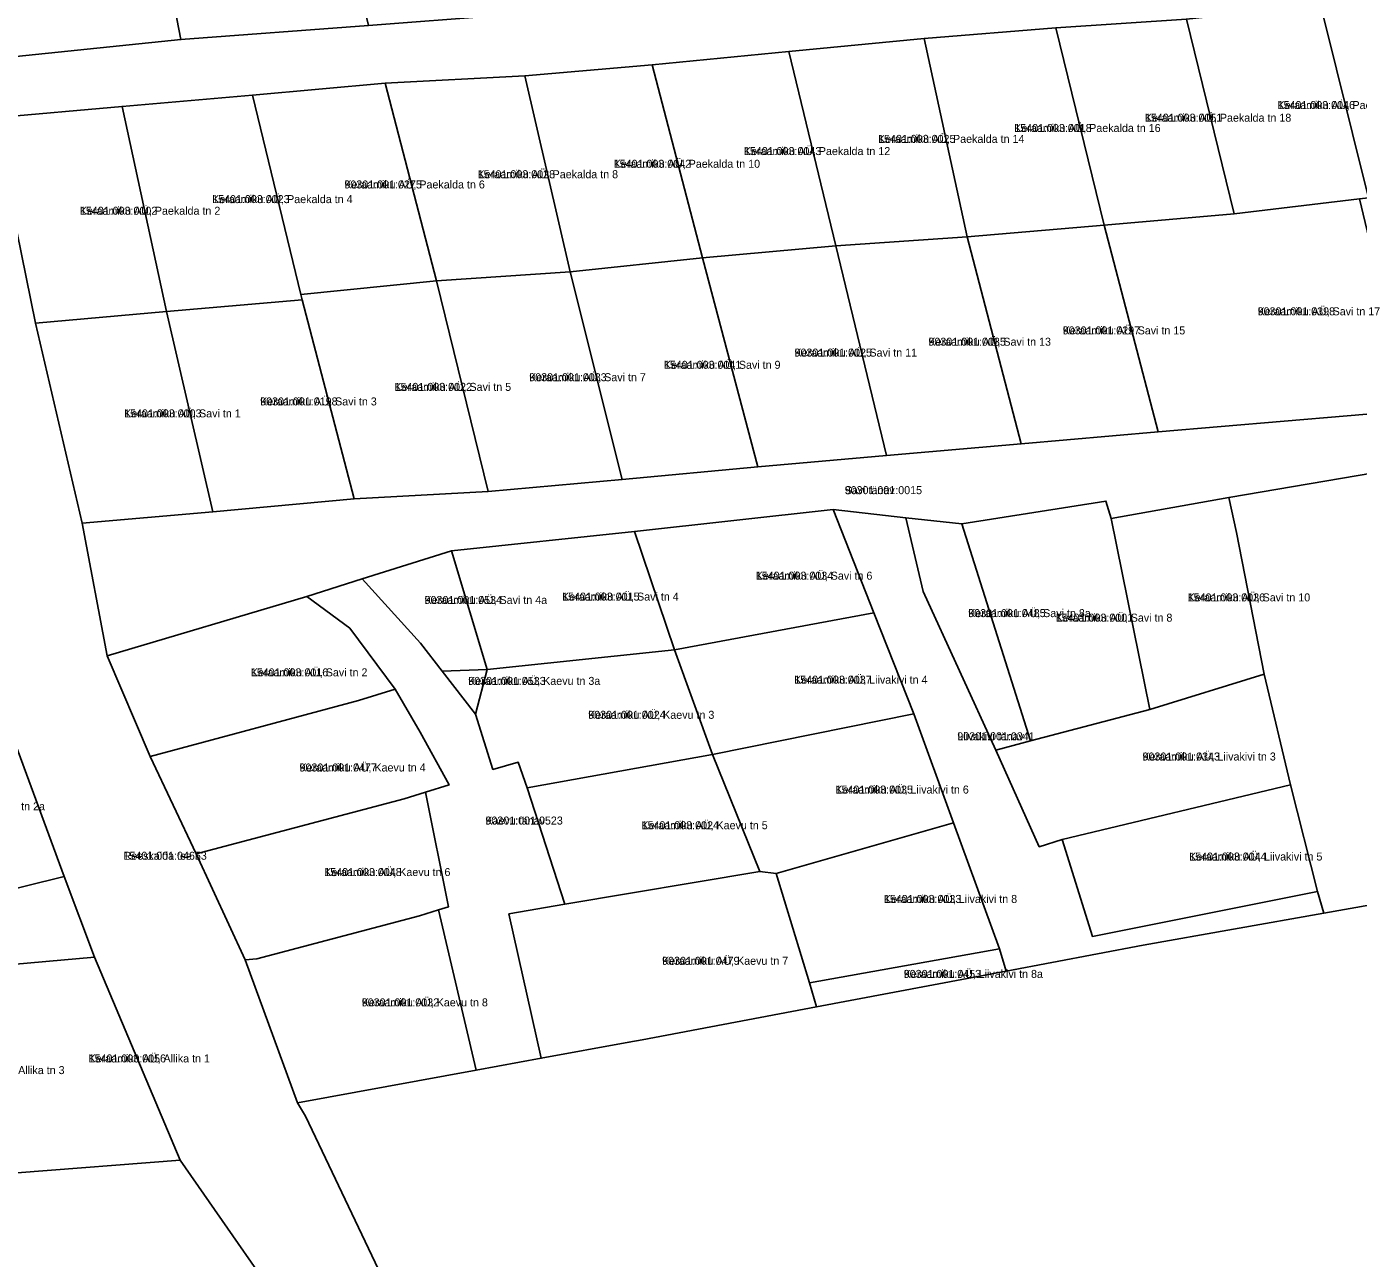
# Model space of a CAD drawing. Extents: x 634518 to 667988, y 6584667 to 6604739.
# Drawn here: x 661923.2 to 662172.8, y 6594554.3 to 6594785.3 of the extents above; entities that cross this region are included whole.
import ezdxf

# ---------------------------------------------------------------- set-up
doc = ezdxf.new("R2010")
doc.units = 0
for name, color, linetype in [('L_AADRESS', 7, 'Continuous'), ('PIIR', 7, 'Continuous'), ('TUNNUS', 7, 'Continuous')]:
    doc.layers.add(name, color=color, linetype=linetype)

msp = doc.modelspace()

# ---------------------------------------------------------------- linework, layer by layer
at = {"layer": 'PIIR'}
for points in [[(661952.09, 6594782.9), (661947.1, 6594808.82), (661942.68, 6594831.72), (661970.02, 6594852.22), (661977.67, 6594824.39), (661987.24, 6594785.58)], [(661911.46, 6594778.72), (661905.34, 6594803.37), (661947.1, 6594808.82), (661952.09, 6594782.9)], [(662165.72, 6594789.4), (662190.16, 6594792.35), (662199.81, 6594755.95), (662174.73, 6594753.23)], [(662149.5, 6594750.24), (662140.59, 6594786.76), (662165.72, 6594789.4), (662174.73, 6594753.23), (662173.04, 6594753.04)], [(662125.18, 6594748.13), (662116.11, 6594785.1), (662140.59, 6594786.76), (662149.5, 6594750.24)], [(662099.49, 6594745.92), (662091.44, 6594783.13), (662116.11, 6594785.1), (662125.18, 6594748.13)], [(662074.83, 6594744.25), (662066.07, 6594780.67), (662091.44, 6594783.13), (662099.49, 6594745.92)], [(662049.88, 6594741.95), (662040.43, 6594778.16), (662066.07, 6594780.67), (662074.83, 6594744.25)], [(661999.99, 6594737.67), (661990.4, 6594774.76), (662016.57, 6594776.09), (662025.06, 6594739.34)], [(662025.06, 6594739.34), (662016.57, 6594776.09), (662040.43, 6594778.16), (662049.88, 6594741.95)], [(661974.6, 6594735.09), (661965.51, 6594772.47), (661990.4, 6594774.76), (661999.99, 6594737.67)], [(661974.84, 6594734.11), (661949.38, 6594731.92), (661941.08, 6594770.36), (661965.51, 6594772.47), (661974.6, 6594735.09)], [(661924.83, 6594729.7), (661916.96, 6594768.23), (661941.08, 6594770.36), (661949.38, 6594731.92)], [(662125.18, 6594748.13), (662149.5, 6594750.24), (662173.04, 6594753.04), (662182.52, 6594713.33), (662135.29, 6594709.35)], [(662135.29, 6594709.35), (662109.62, 6594707.1), (662099.49, 6594745.92), (662125.18, 6594748.13)], [(662049.88, 6594741.95), (662074.83, 6594744.25), (662084.35, 6594704.88), (662060.21, 6594702.77)], [(662074.83, 6594744.25), (662099.49, 6594745.92), (662109.62, 6594707.1), (662084.35, 6594704.88)], [(662034.81, 6594700.43), (662025.06, 6594739.34), (662049.88, 6594741.95), (662060.21, 6594702.77)], [(661999.99, 6594737.67), (662025.06, 6594739.34), (662034.81, 6594700.43), (662009.7, 6594698.16)], [(661974.84, 6594734.11), (661974.6, 6594735.09), (661999.99, 6594737.67), (662009.7, 6594698.16), (661984.55, 6594696.76)], [(661984.55, 6594696.76), (661958.1, 6594694.36), (661949.38, 6594731.92), (661974.84, 6594734.11)], [(661933.59, 6594692.24), (661924.83, 6594729.7), (661949.38, 6594731.92), (661958.1, 6594694.36)], [(662196.65, 6594705.21), (662201.4, 6594681.4), (662236.27, 6594687.1), (662242.98, 6594666.15), (662275.07, 6594673.58), (662277.42, 6594667.41), (662287.3, 6594641.44), (662251.35, 6594634.61), (662246.53, 6594652.01), (662219.88, 6594646.85), (662223.58, 6594629.34), (662214.23, 6594627.56), (662166.33, 6594619.08), (662165.14, 6594623.17), (662160.09, 6594643.16), (662155.13, 6594663.88), (662149.98, 6594690.46), (662148.5, 6594697.01)], [(662111.38, 6594651.37), (662098.46, 6594692.08), (662125.49, 6594696.37), (662126.49, 6594693.07), (662133.73, 6594657.27)], [(662126.49, 6594693.07), (662148.5, 6594697.01), (662149.98, 6594690.46), (662155.13, 6594663.88), (662133.73, 6594657.27)], [(662037.15, 6594690.63), (662074.34, 6594694.77), (662081.99, 6594675.42), (662044.61, 6594668.48)], [(662117.26, 6594632.91), (662122.95, 6594614.73), (662165.14, 6594623.17), (662166.33, 6594619.08), (662132.48, 6594613.08), (662106.77, 6594608.23), (662105.54, 6594612.38), (662096.93, 6594636.02), (662089.46, 6594656.48), (662081.99, 6594675.42), (662074.34, 6594694.77), (662087.97, 6594693.25), (662091.24, 6594679.41), (662104.83, 6594649.65), (662112.99, 6594631.55)], [(662098.46, 6594692.08), (662111.38, 6594651.37), (662104.83, 6594649.65), (662091.24, 6594679.41), (662087.97, 6594693.25)], [(662002.83, 6594687.04), (662037.15, 6594690.63), (662044.61, 6594668.48), (662009.48, 6594664.76)], [(661986.08, 6594681.76), (662002.83, 6594687.04), (662009.48, 6594664.76), (662001.07, 6594664.47), (661997, 6594669.7)], [(661975.68, 6594678.48), (661986.08, 6594681.76), (661997, 6594669.7), (662001.07, 6594664.47), (662007.32, 6594656.43), (662010.57, 6594646.04), (662015.33, 6594647.39), (662016.98, 6594642.58), (662024.04, 6594620.8), (662013.58, 6594618.94), (662019.64, 6594591.87), (662007.46, 6594589.64), (662000.39, 6594619.68), (662002.23, 6594620.25), (661997.93, 6594641.79), (662002.37, 6594643.12), (661996.93, 6594653.01), (661992.27, 6594661.09), (661983.76, 6594672.52)], [(661946.35, 6594648.49), (661938.29, 6594667.33), (661975.68, 6594678.48), (661983.76, 6594672.52), (661992.27, 6594661.09), (661985.42, 6594658.98)], [(662051.73, 6594648.83), (662044.61, 6594668.48), (662081.99, 6594675.42), (662089.46, 6594656.48)], [(661772.99, 6594666.58), (661777.22, 6594667.05), (661784.51, 6594671.09), (661784.65, 6594668.87), (661786.84, 6594636.17), (661786.72, 6594613.48), (661829.26, 6594616.38), (661871.06, 6594617.08), (661885.08, 6594618.37), (661907.96, 6594620.48), (661930.24, 6594625.96), (661935.9, 6594610.85), (661917.6, 6594609.21), (661893.7, 6594606.91), (661868.98, 6594606.11), (661844.31, 6594605.15), (661819.12, 6594604.56), (661794.19, 6594601.28), (661770.12, 6594599.82), (661769.01, 6594610.95), (661778.3, 6594611.7), (661776.11, 6594638.94)], [(662009.48, 6594664.76), (662044.61, 6594668.48), (662051.73, 6594648.83), (662016.98, 6594642.58), (662015.33, 6594647.39), (662010.57, 6594646.04), (662007.32, 6594656.43)], [(662001.07, 6594664.47), (662009.48, 6594664.76), (662007.32, 6594656.43)], [(662133.73, 6594657.27), (662155.13, 6594663.88), (662160.09, 6594643.16), (662117.26, 6594632.91), (662112.99, 6594631.55), (662104.83, 6594649.65), (662111.38, 6594651.37)], [(661946.35, 6594648.49), (661985.42, 6594658.98), (661992.27, 6594661.09), (661996.93, 6594653.01), (662002.37, 6594643.12), (661997.93, 6594641.79), (661993.97, 6594640.55), (661954.96, 6594630.21)], [(661918.31, 6594658.38), (661930.24, 6594625.96), (661907.96, 6594620.48), (661885.08, 6594618.37), (661877.59, 6594645.87), (661910.92, 6594655.93)], [(662051.73, 6594648.83), (662089.46, 6594656.48), (662096.93, 6594636.02), (662063.65, 6594626.54), (662060.61, 6594626.92)], [(662024.04, 6594620.8), (662016.98, 6594642.58), (662051.73, 6594648.83), (662060.61, 6594626.92)], [(661966.31, 6594610.54), (661964.17, 6594610.3), (661954.96, 6594630.21), (661993.97, 6594640.55), (661997.93, 6594641.79), (662002.23, 6594620.25), (662000.39, 6594619.68), (661996.85, 6594618.58)], [(662122.95, 6594614.73), (662117.26, 6594632.91), (662160.09, 6594643.16), (662165.14, 6594623.17)], [(662069.93, 6594605.99), (662063.65, 6594626.54), (662096.93, 6594636.02), (662105.54, 6594612.38)], [(662024.04, 6594620.8), (662060.61, 6594626.92), (662063.65, 6594626.54), (662069.93, 6594605.99), (662071.21, 6594601.5), (662038.56, 6594595.33), (662036.07, 6594594.87), (662019.64, 6594591.87), (662013.58, 6594618.94)], [(661964.17, 6594610.3), (661966.31, 6594610.54), (661996.85, 6594618.58), (662000.39, 6594619.68), (662007.46, 6594589.64), (661973.97, 6594583.52)], [(662106.77, 6594608.23), (662071.21, 6594601.5), (662069.93, 6594605.99), (662105.54, 6594612.38)], [(661917.6, 6594609.21), (661935.9, 6594610.85), (661951.99, 6594572.75), (661921.4, 6594570.39)], [(662053.02, 6594314.87), (662030.82, 6594306.94), (662002.72, 6594304.76), (661969.65, 6594310.52), (661952.9, 6594316.01), (661931.36, 6594332.48), (661900.65, 6594357.08), (661733.61, 6594488.34), (661689.17, 6594526.17), (661707.96, 6594555.4), (661749.99, 6594558.94), (661771.61, 6594560.7), (661796.73, 6594562.72), (661821.55, 6594564.42), (661846.63, 6594565.93), (661871.21, 6594567.37), (661896.29, 6594568.87), (661921.4, 6594570.39), (661951.99, 6594572.75), (662000.32, 6594503.25), (662048.8, 6594406.38), (662016.31, 6594387.1)]]:
    msp.add_lwpolyline(points, close=True, dxfattribs=at)
for points in [[(662190.16, 6594792.35), (662165.72, 6594789.4), (662140.59, 6594786.76), (662116.11, 6594785.1), (662091.44, 6594783.13), (662066.07, 6594780.67), (662040.43, 6594778.16), (662016.57, 6594776.09), (661990.4, 6594774.76), (661965.51, 6594772.47), (661941.08, 6594770.36), (661916.96, 6594768.23), (661911.46, 6594778.72), (661952.09, 6594782.9), (661987.24, 6594785.58), (662011.68, 6594787.45), (662037.26, 6594789.4), (662062.13, 6594791.6), (662088.56, 6594794.22), (662112.45, 6594796.74), (662122.68, 6594798.22), (662147.35, 6594799.74), (662172.57, 6594802.15), (662179.59, 6594802.52)], [(661916.96, 6594768.23), (661924.83, 6594729.7), (661933.59, 6594692.24), (661938.29, 6594667.33), (661946.35, 6594648.49), (661954.96, 6594630.21), (661964.17, 6594610.3), (661973.97, 6594583.52), (661975.47, 6594581.01), (662010.27, 6594507.9)], [(662010.27, 6594507.9), (661975.47, 6594581.01), (661973.97, 6594583.52), (662007.46, 6594589.64), (662019.64, 6594591.87), (662036.07, 6594594.87), (662038.56, 6594595.33), (662071.21, 6594601.5), (662106.77, 6594608.23), (662132.48, 6594613.08), (662166.33, 6594619.08), (662214.23, 6594627.56), (662223.58, 6594629.34), (662238.85, 6594632.24), (662251.35, 6594634.61), (662287.3, 6594641.44), (662287.9, 6594641.55), (662291.93, 6594642.32), (662292.94, 6594642.5), (662297.43, 6594643.28), (662328.61, 6594648.73), (662329.92, 6594651.1), (662407.03, 6594740.17)], [(662196.65, 6594705.21), (662148.5, 6594697.01), (662126.49, 6594693.07), (662125.49, 6594696.37), (662098.46, 6594692.08), (662087.97, 6594693.25), (662074.34, 6594694.77), (662037.15, 6594690.63), (662002.83, 6594687.04), (661986.08, 6594681.76), (661975.68, 6594678.48), (661938.29, 6594667.33), (661933.59, 6594692.24), (661958.1, 6594694.36), (661984.55, 6594696.76), (662009.7, 6594698.16), (662034.81, 6594700.43), (662060.21, 6594702.77), (662084.35, 6594704.88), (662109.62, 6594707.1), (662135.29, 6594709.35), (662182.52, 6594713.33)], [(662000.32, 6594503.25), (661951.99, 6594572.75), (661935.9, 6594610.85), (661930.24, 6594625.96), (661918.31, 6594658.38)]]:
    msp.add_lwpolyline(points, dxfattribs=at)

# ---------------------------------------------------------------- texts
at = {"layer": 'L_AADRESS'}
for s, p in [('Keraamiku AÜ, Paekalda tn 20', (662157.66, 6594769.88)), ('Keraamiku AÜ, Paekalda tn 18', (662132.8, 6594767.51)), ('Keraamiku AÜ, Paekalda tn 16', (662108.31, 6594765.58)), ('Keraamiku AÜ, Paekalda tn 14', (662082.78, 6594763.54)), ('Keraamiku AÜ, Paekalda tn 12', (662057.63, 6594761.25)), ('Keraamiku AÜ, Paekalda tn 8', (662007.73, 6594756.91)), ('Keraamiku AÜ, Paekalda tn 10', (662033.23, 6594758.87)), ('Keraamiku AÜ, Paekalda tn 6', (661982.75, 6594754.99)), ('Keraamiku AÜ, Paekalda tn 4', (661957.96, 6594752.24)), ('Keraamiku AÜ, Paekalda tn 2', (661933.17, 6594750.06)), ('Keraamiku AÜ, Savi tn 17', (662153.93, 6594731.2)), ('Keraamiku AÜ, Savi tn 15', (662117.39, 6594727.62)), ('Keraamiku AÜ, Savi tn 13', (662092.22, 6594725.5)), ('Keraamiku AÜ, Savi tn 11', (662067.12, 6594723.46)), ('Keraamiku AÜ, Savi tn 9', (662042.64, 6594721.17)), ('Keraamiku AÜ, Savi tn 5', (661992.15, 6594717.03)), ('Keraamiku AÜ, Savi tn 7', (662017.4, 6594718.84)), ('Keraamiku AÜ, Savi tn 1', (661941.46, 6594712.06)), ('Keraamiku AÜ, Savi tn 3', (661966.96, 6594714.3)), ('Savi tänav', (662076.52, 6594697.66)), ('Keraamiku AÜ, Savi tn 6', (662059.86, 6594681.62)), ('Keraamiku AÜ, Savi tn 4a', (661997.78, 6594677.07)), ('Keraamiku AÜ, Savi tn 4', (662023.56, 6594677.7)), ('Keraamiku AÜ, Savi tn 10', (662140.81, 6594677.55)), ('Keraamiku AÜ, Savi tn 8a', (662099.68, 6594674.6)), ('Keraamiku AÜ, Savi tn 8', (662116.09, 6594673.75)), ('Keraamiku AÜ, Savi tn 2', (661965.21, 6594663.49)), ('Keraamiku AÜ, Liivakivi tn 4', (662067.07, 6594662.12)), ('Keraamiku AÜ, Kaevu tn 3a', (662005.96, 6594661.89)), ('Keraamiku AÜ, Kaevu tn 3', (662028.45, 6594655.53)), ('Liivakivi tänav', (662097.63, 6594651.5)), ('Keraamiku AÜ, Liivakivi tn 3', (662132.35, 6594647.71)), ('Keraamiku AÜ, Kaevu tn 4', (661974.33, 6594645.65)), ('Keraamiku AÜ, Liivakivi tn 6', (662074.81, 6594641.51)), ('Keraamiku AÜ, Järve tn 2a', (661902.65, 6594638.38)), ('Kaevu tänav', (662009.18, 6594635.7)), ('Keraamiku AÜ, Kaevu tn 5', (662038.45, 6594634.82)), ('Reeskalda tee L3', (661941.34, 6594629.1)), ('Keraamiku AÜ, Liivakivi tn 5', (662141.09, 6594628.95)), ('Keraamiku AÜ, Kaevu tn 6', (661978.98, 6594626.04)), ('Keraamiku AÜ, Liivakivi tn 8', (662083.87, 6594621)), ('Keraamiku AÜ, Kaevu tn 7', (662042.3, 6594609.4)), ('Keraamiku AÜ, Liivakivi tn 8a', (662087.59, 6594606.94)), ('Keraamiku AÜ, Kaevu tn 8', (661986, 6594601.6)), ('Keraamiku AÜ, Allika tn 1', (661934.8, 6594591.09)), ('Keraamiku AÜ, Allika tn 3', (661907.55, 6594588.9))]:
    msp.add_text(s, height=1.5, dxfattribs=at).set_placement(p)
at = {"layer": 'TUNNUS'}
for s, p in [('15401:003:0046', (662157.66, 6594769.88)), ('15401:003:0051', (662132.8, 6594767.51)), ('15401:003:0018', (662108.31, 6594765.58)), ('15401:003:0025', (662082.78, 6594763.54)), ('15401:003:0043', (662057.63, 6594761.25)), ('15401:003:0042', (662033.23, 6594758.87)), ('90301:001:0275', (661982.75, 6594754.99)), ('15401:003:0028', (662007.73, 6594756.91)), ('15401:003:0023', (661957.96, 6594752.24)), ('15401:003:0002', (661933.17, 6594750.06)), ('90301:001:0398', (662153.93, 6594731.2)), ('90301:001:0297', (662117.39, 6594727.62)), ('90301:001:0035', (662092.22, 6594725.5)), ('90301:001:0025', (662067.12, 6594723.46)), ('15401:003:0041', (662042.64, 6594721.17)), ('90301:001:0083', (662017.4, 6594718.84)), ('15401:003:0022', (661992.15, 6594717.03)), ('90301:001:0198', (661966.96, 6594714.3)), ('15401:003:0003', (661941.46, 6594712.06)), ('90301:001:0015', (662076.52, 6594697.66)), ('15401:003:0034', (662059.86, 6594681.62)), ('15401:003:0015', (662023.56, 6594677.7)), ('15401:003:0036', (662140.81, 6594677.55)), ('90301:001:0534', (661997.78, 6594677.07)), ('90301:001:0485', (662099.68, 6594674.6)), ('15401:003:0001', (662116.09, 6594673.75)), ('15401:003:0016', (661965.21, 6594663.49)), ('90301:001:0533', (662005.96, 6594661.89)), ('15401:003:0037', (662067.07, 6594662.12)), ('90301:001:0024', (662028.45, 6594655.53)), ('90301:001:0341', (662097.63, 6594651.5)), ('90301:001:0343', (662132.35, 6594647.71)), ('90301:001:0477', (661974.33, 6594645.65)), ('15401:003:0035', (662074.81, 6594641.51)), ('90301:001:0523', (662009.18, 6594635.7)), ('15401:003:0024', (662038.45, 6594634.82)), ('15401:001:0465', (661941.34, 6594629.1)), ('15401:003:0044', (662141.09, 6594628.95)), ('15401:003:0048', (661978.98, 6594626.04)), ('15401:003:0033', (662083.87, 6594621)), ('90301:001:0479', (662042.3, 6594609.4)), ('90301:001:0453', (662087.59, 6594606.94)), ('90301:001:0032', (661986, 6594601.6)), ('15401:003:0056', (661934.8, 6594591.09))]:
    msp.add_text(s, height=1.5, dxfattribs=at).set_placement(p)

doc.saveas('drawing.dxf')
